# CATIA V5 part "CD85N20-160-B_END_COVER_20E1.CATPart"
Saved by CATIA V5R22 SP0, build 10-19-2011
Part number: CD85N20-160-B_END_COVER_20E1
Revision: ANY
Definition: UNKNOWN
Nomenclature: CD85N20-160-B_END_COVER_20E1
Source: Unknown
Bounding box of the stored display mesh (mm): x -12 to 12, y -12 to 12, z 0 to 35
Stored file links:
  U:\S9A\PER\CAO\Assemblage\Reservoir_Boite\Verin\Test_Poussoir_2\Test\CD85N20-160-B_END_COVER_20E1.CATPart
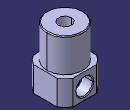
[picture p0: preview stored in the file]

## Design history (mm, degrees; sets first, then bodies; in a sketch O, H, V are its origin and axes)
Body1 "Chamfer1" (main body)
  Solid1: solid without history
